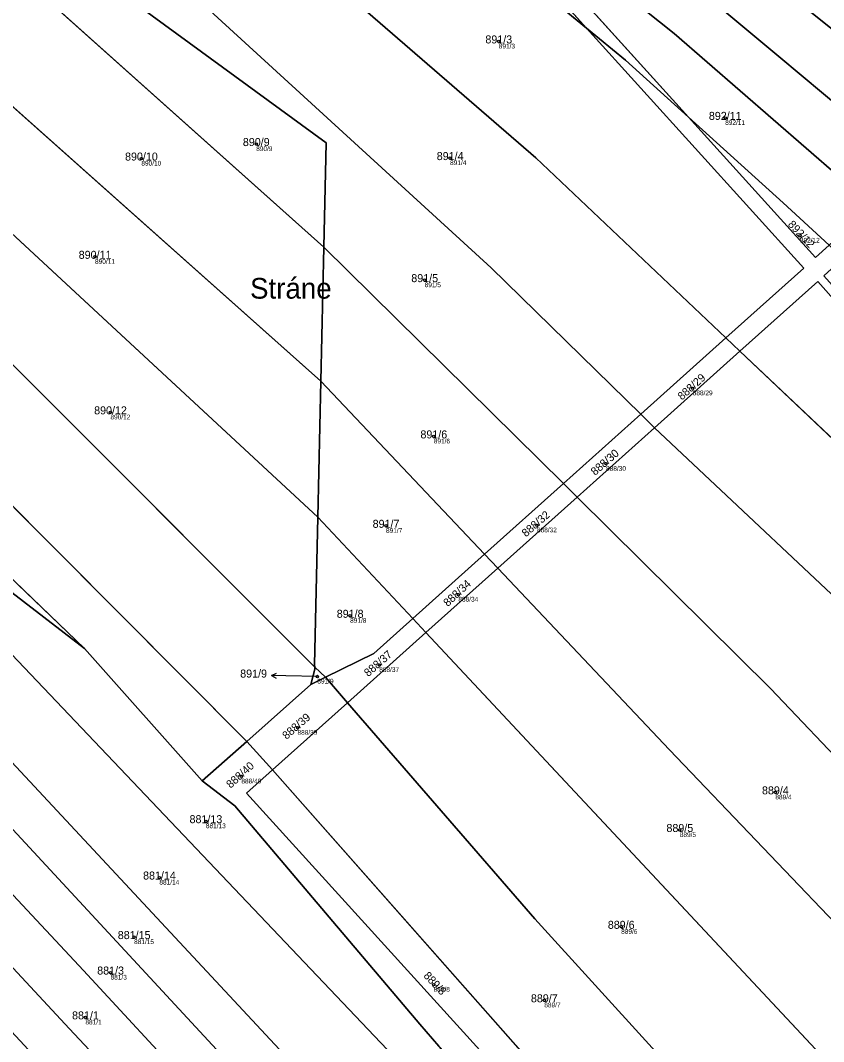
# Model space of a CAD drawing. Extents: x -603967 to -594699, y -1179315 to -1165625.
# Drawn here: x -597688.8 to -597518.2, y -1171449.4 to -1171232.5 of the extents above; entities that cross this region are included whole.
import ezdxf

# ---------------------------------------------------------------- set-up
doc = ezdxf.new("R2010")
doc.units = 0
for name, color, linetype in [('Definiční body', 7, 'Continuous'), ('Hranice parcel', 7, 'Continuous'), ('Parcelní čísla', 7, 'Continuous'), ('Polygon parcely', 7, 'Continuous'), ('Pop  PČ popisy', 7, 'Continuous')]:
    doc.layers.add(name, color=color, linetype=linetype)

msp = doc.modelspace()

# ---------------------------------------------------------------- linework, layer by layer
at = {"layer": 'Definiční body'}
for centre in [(-597587.23, -1171236.96994), (-597539.14, -1171253.20994), (-597638.73, -1171258.76994), (-597663.12, -1171261.84994), (-597597.56, -1171261.74994), (-597523.28, -1171278.20994), (-597672.96, -1171282.71994), (-597602.96, -1171287.67994), (-597546.03, -1171310.63994), (-597669.68, -1171315.75994), (-597601.02, -1171320.86994), (-597564.44, -1171326.67994), (-597579.11, -1171339.74994), (-597611.17, -1171339.85994), (-597595.8, -1171354.45994), (-597618.79, -1171358.96994), (-597612.61, -1171369.41994), (-597625.75, -1171371.86994), (-597629.96, -1171382.74994), (-597641.88, -1171393.08994), (-597528.49, -1171396.47994), (-597649.42, -1171402.59994), (-597548.78, -1171404.46994), (-597659.29, -1171414.56994), (-597561.23, -1171425.03994), (-597664.66, -1171427.21994), (-597669.66, -1171434.74994), (-597601.07, -1171437.31994), (-597577.56, -1171440.64994), (-597675, -1171444.27994)]:
    msp.add_circle(centre, 0.25, dxfattribs=at)
at = {"layer": 'Hranice parcel'}
for p, q in [((-597638.82, -1171176.32), (-597568.57, -1171234.15)), ((-597613.57, -1171184.37), (-597568.57, -1171234.15)), ((-597546.95, -1171253.04), (-597596.69, -1171198.02)), ((-597694.09, -1171218.3), (-597624.36, -1171280.64)), ((-597710.45, -1171233.05), (-597624.99, -1171309.14)), ((-597724.86, -1171246.07), (-597625.64, -1171338.04)), ((-597738.23, -1171257.8), (-597626.31, -1171369.88)), ((-597753.72, -1171272.15), (-597640.75, -1171385.64)), ((-597624.99, -1171309.14), (-597624.36, -1171280.64)), ((-597624.36, -1171280.64), (-597573.47, -1171330.88)), ((-597538.99, -1171299.95), (-597557.08, -1171316.18)), ((-597538.99, -1171299.95), (-597536.01, -1171302.78)), ((-597740.92, -1171302.84), (-597675.16, -1171365.94)), ((-597554.16, -1171319.04), (-597536.01, -1171302.78)), ((-597536.01, -1171302.78), (-597441.73, -1171392.05)), ((-597625.64, -1171338.04), (-597624.99, -1171309.14)), ((-597624.99, -1171309.14), (-597590.23, -1171345.9)), ((-597557.08, -1171316.18), (-597573.47, -1171330.88)), ((-597557.08, -1171316.18), (-597554.16, -1171319.04)), ((-597570.57, -1171333.75), (-597554.16, -1171319.04)), ((-597573.47, -1171330.88), (-597590.23, -1171345.9)), ((-597573.47, -1171330.88), (-597570.57, -1171333.75)), ((-597587.43, -1171348.86), (-597570.57, -1171333.75)), ((-597625.64, -1171338.04), (-597605.49, -1171359.58)), ((-597590.23, -1171345.9), (-597605.49, -1171359.58)), ((-597590.23, -1171345.9), (-597587.43, -1171348.86)), ((-597602.71, -1171362.55), (-597587.43, -1171348.86)), ((-597605.49, -1171359.58), (-597602.71, -1171362.55)), ((-597619.35, -1171377.46), (-597602.71, -1171362.55)), ((-597602.71, -1171362.55), (-597503.62, -1171468.5)), ((-597650.23, -1171394.06), (-597675.16, -1171365.94)), ((-597626.31, -1171369.88), (-597624.05, -1171372.04)), ((-597624.05, -1171372.04), (-597627.15, -1171373.56)), ((-597624.05, -1171372.04), (-597619.35, -1171377.46)), ((-597627.15, -1171373.56), (-597640.75, -1171385.64)), ((-597635.25, -1171391.71), (-597619.35, -1171377.46)), ((-597640.75, -1171385.64), (-597650.23, -1171394.06)), ((-597640.75, -1171385.64), (-597635.25, -1171391.71)), ((-597635.25, -1171391.71), (-597532.51, -1171508.06))]:
    msp.add_line(p, q, dxfattribs=at)
for points in [[(-597619, -1171152.15), (-597495.03, -1171251.51), (-597490.18, -1171255.6)], [(-597625.73, -1171158.41), (-597527.76, -1171240.19), (-597499.3, -1171263.96)], [(-597653.35, -1171197.65), (-597579.35, -1171261.73), (-597538.99, -1171299.95)], [(-597596.69, -1171198.02), (-597549.97, -1171235.28), (-597507.9, -1171271.83)], [(-597675.9, -1171205.37), (-597588.87, -1171285.05), (-597557.08, -1171316.18)], [(-597624.36, -1171280.64), (-597623.87, -1171258.48), (-597687.3, -1171212.14)], [(-597568.57, -1171234.15), (-597560.31, -1171240.95), (-597546.95, -1171253.04)], [(-597568.57, -1171234.15), (-597522.47, -1171285.14), (-597538.99, -1171299.95)], [(-597517.08, -1171280.25), (-597519.96, -1171282.89), (-597546.95, -1171253.04)], [(-597546.95, -1171253.04), (-597526.84, -1171271.23), (-597517.08, -1171280.25)], [(-597785.88, -1171273.72), (-597698.87, -1171358.66), (-597539.28, -1171526.49)], [(-597798.56, -1171286.2), (-597707.11, -1171372.43), (-597548.07, -1171543.16)], [(-597536.01, -1171302.78), (-597519.45, -1171287.94), (-597434.29, -1171384), (-597441.73, -1171392.05)], [(-597557.85, -1171562.02), (-597628.52, -1171485.03), (-597675.4, -1171434.3), (-597721.26, -1171385.23), (-597762.22, -1171345.08), (-597817.7, -1171293.77)], [(-597553.17, -1171552.83), (-597611.02, -1171490.2), (-597718.71, -1171373.87), (-597804.91, -1171293.86)], [(-597823.57, -1171301.41), (-597729.77, -1171391.38), (-597678.47, -1171446.61), (-597562.3, -1171570.48)], [(-597675.16, -1171365.94), (-597731.41, -1171322.64), (-597740.92, -1171302.84)], [(-597820.81, -1171313.44), (-597733.25, -1171401.44), (-597680.8, -1171457.94), (-597637.47, -1171505.28), (-597595.8, -1171550.59), (-597567.3, -1171579.99)], [(-597554.16, -1171319.04), (-597503.7, -1171366.48), (-597459.73, -1171411.51)], [(-597570.57, -1171333.75), (-597529.49, -1171374.44), (-597476.23, -1171430.49)], [(-597626.31, -1171369.88), (-597626.33, -1171369.4), (-597625.64, -1171338.04)], [(-597587.43, -1171348.86), (-597550.95, -1171387.45), (-597491.29, -1171449.91)], [(-597605.49, -1171359.58), (-597613.74, -1171366.98), (-597624.05, -1171372.04)], [(-597627.15, -1171373.56), (-597626.28, -1171370.28), (-597626.31, -1171369.88)], [(-597619.35, -1171377.46), (-597579.59, -1171423.33), (-597518.33, -1171490.67)], [(-597532.51, -1171508.06), (-597536.12, -1171512.02), (-597640.76, -1171396.65), (-597635.25, -1171391.71)], [(-597599.98, -1171450.36), (-597604.01, -1171445.75), (-597643.27, -1171399.35), (-597650.23, -1171394.06)]]:
    msp.add_lwpolyline(points, dxfattribs=at)
at = {"layer": 'Polygon parcely'}
for points in [[(-597490.18, -1171255.6), (-597481.53, -1171247.68), (-597611.54, -1171142.36), (-597619, -1171152.15), (-597495.03, -1171251.51)], [(-597527.76, -1171240.19), (-597499.3, -1171263.96), (-597490.18, -1171255.6), (-597495.03, -1171251.51), (-597619, -1171152.15), (-597619.88, -1171153.3), (-597625.73, -1171158.41)], [(-597507.9, -1171271.83), (-597499.3, -1171263.96), (-597527.76, -1171240.19), (-597625.73, -1171158.41), (-597629.36, -1171161.92), (-597596.69, -1171198.02), (-597549.97, -1171235.28)], [(-597568.57, -1171234.15), (-597613.57, -1171184.37), (-597635.17, -1171166.91), (-597638.82, -1171176.32)], [(-597579.35, -1171261.73), (-597538.99, -1171299.95), (-597522.47, -1171285.14), (-597568.57, -1171234.15), (-597638.82, -1171176.32), (-597638.29, -1171186.95), (-597641.25, -1171190.94), (-597653.35, -1171197.65)], [(-597560.31, -1171240.95), (-597546.95, -1171253.04), (-597596.69, -1171198.02), (-597613.57, -1171184.37), (-597568.57, -1171234.15)], [(-597588.87, -1171285.05), (-597557.08, -1171316.18), (-597538.99, -1171299.95), (-597579.35, -1171261.73), (-597653.35, -1171197.65), (-597671.49, -1171204.29), (-597675.9, -1171205.37)], [(-597517.08, -1171280.25), (-597507.9, -1171271.83), (-597549.97, -1171235.28), (-597596.69, -1171198.02), (-597546.95, -1171253.04), (-597526.84, -1171271.23)], [(-597573.47, -1171330.88), (-597557.08, -1171316.18), (-597588.87, -1171285.05), (-597675.9, -1171205.37), (-597687.3, -1171212.14), (-597623.87, -1171258.48), (-597624.36, -1171280.64)], [(-597694.09, -1171218.3), (-597624.36, -1171280.64), (-597623.87, -1171258.48), (-597687.3, -1171212.14)], [(-597710.45, -1171233.05), (-597624.99, -1171309.14), (-597624.36, -1171280.64), (-597694.09, -1171218.3)], [(-597625.64, -1171338.04), (-597624.99, -1171309.14), (-597710.45, -1171233.05), (-597710.47, -1171233.07), (-597724.86, -1171246.07)], [(-597519.45, -1171287.94), (-597434.29, -1171384), (-597441.73, -1171392.05), (-597438.05, -1171395.53), (-597416.59, -1171374.28), (-597420.76, -1171370.38), (-597432.83, -1171382.26), (-597518.17, -1171286.79), (-597514.06, -1171283.04), (-597517.08, -1171280.25), (-597519.96, -1171282.89), (-597546.95, -1171253.04), (-597560.31, -1171240.95), (-597568.57, -1171234.15), (-597522.47, -1171285.14), (-597538.99, -1171299.95), (-597536.01, -1171302.78)], [(-597625.64, -1171338.04), (-597724.86, -1171246.07), (-597738.23, -1171257.8), (-597626.31, -1171369.88), (-597626.33, -1171369.4)], [(-597546.95, -1171253.04), (-597519.96, -1171282.89), (-597517.08, -1171280.25), (-597526.84, -1171271.23)], [(-597640.75, -1171385.64), (-597627.15, -1171373.56), (-597626.28, -1171370.28), (-597626.31, -1171369.88), (-597738.23, -1171257.8), (-597753.72, -1171272.15)], [(-597539.28, -1171526.49), (-597536.95, -1171522.06), (-597571.65, -1171482.78), (-597599.98, -1171450.36), (-597604.01, -1171445.75), (-597643.27, -1171399.35), (-597650.23, -1171394.06), (-597675.16, -1171365.94), (-597731.41, -1171322.64), (-597740.92, -1171302.84), (-597777.31, -1171267.91), (-597785.88, -1171273.72), (-597698.87, -1171358.66)], [(-597675.16, -1171365.94), (-597650.23, -1171394.06), (-597640.75, -1171385.64), (-597753.72, -1171272.15), (-597755.07, -1171273.4), (-597740.92, -1171302.84)], [(-597707.11, -1171372.43), (-597548.07, -1171543.16), (-597539.28, -1171526.49), (-597698.87, -1171358.66), (-597785.88, -1171273.72), (-597791.14, -1171277.25), (-597798.56, -1171286.2)], [(-597590.23, -1171345.9), (-597573.47, -1171330.88), (-597624.36, -1171280.64), (-597624.99, -1171309.14)], [(-597548.07, -1171543.16), (-597707.11, -1171372.43), (-597798.56, -1171286.2), (-597804.91, -1171293.86), (-597718.71, -1171373.87), (-597611.02, -1171490.2), (-597553.17, -1171552.83)], [(-597441.73, -1171392.05), (-597434.29, -1171384), (-597519.45, -1171287.94), (-597536.01, -1171302.78)], [(-597675.4, -1171434.3), (-597721.26, -1171385.23), (-597762.22, -1171345.08), (-597817.7, -1171293.77), (-597823.57, -1171301.41), (-597729.77, -1171391.38), (-597678.47, -1171446.61), (-597562.3, -1171570.48), (-597557.85, -1171562.02), (-597628.52, -1171485.03)], [(-597553.17, -1171552.83), (-597611.02, -1171490.2), (-597718.71, -1171373.87), (-597804.91, -1171293.86), (-597808.81, -1171298.6), (-597817.7, -1171293.77), (-597762.22, -1171345.08), (-597721.26, -1171385.23), (-597675.4, -1171434.3), (-597628.52, -1171485.03), (-597557.85, -1171562.02)], [(-597538.99, -1171299.95), (-597557.08, -1171316.18), (-597554.16, -1171319.04), (-597536.01, -1171302.78)], [(-597733.25, -1171401.44), (-597680.8, -1171457.94), (-597637.47, -1171505.28), (-597595.8, -1171550.59), (-597567.3, -1171579.99), (-597562.3, -1171570.48), (-597678.47, -1171446.61), (-597729.77, -1171391.38), (-597823.57, -1171301.41), (-597820.81, -1171313.44)], [(-597740.92, -1171302.84), (-597731.41, -1171322.64), (-597675.16, -1171365.94)], [(-597503.7, -1171366.48), (-597459.73, -1171411.51), (-597441.73, -1171392.05), (-597536.01, -1171302.78), (-597554.16, -1171319.04)], [(-597590.23, -1171345.9), (-597624.99, -1171309.14), (-597625.64, -1171338.04), (-597605.49, -1171359.58)], [(-597572.35, -1171589.98), (-597567.48, -1171580.33), (-597567.3, -1171579.99), (-597595.8, -1171550.59), (-597637.47, -1171505.28), (-597680.8, -1171457.94), (-597733.25, -1171401.44), (-597820.81, -1171313.44), (-597818.75, -1171330.98), (-597742.73, -1171403.86)], [(-597557.08, -1171316.18), (-597573.47, -1171330.88), (-597570.57, -1171333.75), (-597554.16, -1171319.04)], [(-597476.23, -1171430.49), (-597467.74, -1171420.18), (-597459.73, -1171411.51), (-597503.7, -1171366.48), (-597554.16, -1171319.04), (-597570.57, -1171333.75), (-597529.49, -1171374.44)], [(-597590.23, -1171345.9), (-597587.43, -1171348.86), (-597570.57, -1171333.75), (-597573.47, -1171330.88)], [(-597491.29, -1171449.91), (-597487.43, -1171444.09), (-597476.23, -1171430.49), (-597529.49, -1171374.44), (-597570.57, -1171333.75), (-597587.43, -1171348.86), (-597550.95, -1171387.45)], [(-597624.05, -1171372.04), (-597613.74, -1171366.98), (-597605.49, -1171359.58), (-597625.64, -1171338.04), (-597626.33, -1171369.4), (-597626.31, -1171369.88)], [(-597587.43, -1171348.86), (-597590.23, -1171345.9), (-597605.49, -1171359.58), (-597602.71, -1171362.55)], [(-597503.62, -1171468.5), (-597491.29, -1171449.91), (-597550.95, -1171387.45), (-597587.43, -1171348.86), (-597602.71, -1171362.55)], [(-597613.74, -1171366.98), (-597624.05, -1171372.04), (-597619.35, -1171377.46), (-597602.71, -1171362.55), (-597605.49, -1171359.58)], [(-597579.59, -1171423.33), (-597518.33, -1171490.67), (-597503.62, -1171468.5), (-597602.71, -1171362.55), (-597619.35, -1171377.46)], [(-597627.15, -1171373.56), (-597624.05, -1171372.04), (-597626.31, -1171369.88), (-597626.28, -1171370.28)], [(-597640.75, -1171385.64), (-597635.25, -1171391.71), (-597619.35, -1171377.46), (-597624.05, -1171372.04), (-597627.15, -1171373.56)], [(-597635.25, -1171391.71), (-597532.51, -1171508.06), (-597522.8, -1171497.41), (-597518.33, -1171490.67), (-597579.59, -1171423.33), (-597619.35, -1171377.46)], [(-597536.12, -1171512.02), (-597640.76, -1171396.65), (-597635.25, -1171391.71), (-597640.75, -1171385.64), (-597650.23, -1171394.06), (-597643.27, -1171399.35), (-597604.01, -1171445.75), (-597599.98, -1171450.36), (-597530.86, -1171523.81), (-597529.58, -1171521.69), (-597525.22, -1171516.31), (-597532.51, -1171508.06)], [(-597635.25, -1171391.71), (-597640.76, -1171396.65), (-597536.12, -1171512.02), (-597532.51, -1171508.06)]]:
    msp.add_lwpolyline(points, close=True, dxfattribs=at)
at = {"layer": 'Pop  PČ popisy'}
for p, q in [((-597635.461, -1171371.678), (-597634.45, -1171371.194)), ((-597632.46, -1171371.73), (-597635.461, -1171371.678)), ((-597635.461, -1171371.678), (-597634.468, -1171372.196)), ((-597625.75, -1171371.87), (-597632.46, -1171371.73))]:
    msp.add_line(p, q, dxfattribs=at)

# ---------------------------------------------------------------- texts
at = {"layer": 'Definiční body'}
for s, p in [('891/3', (-597587.23, -1171238.459)), ('892/11', (-597539.14, -1171254.699)), ('890/9', (-597638.73, -1171260.259)), ('890/10', (-597663.12, -1171263.339)), ('891/4', (-597597.56, -1171263.239)), ('892/12', (-597523.28, -1171279.699)), ('890/11', (-597672.96, -1171284.209)), ('891/5', (-597602.96, -1171289.169)), ('888/29', (-597546.03, -1171312.129)), ('890/12', (-597669.68, -1171317.249)), ('891/6', (-597601.02, -1171322.359)), ('888/30', (-597564.44, -1171328.169)), ('891/7', (-597611.17, -1171341.349)), ('888/32', (-597579.11, -1171341.239)), ('888/34', (-597595.8, -1171355.949)), ('891/8', (-597618.79, -1171360.459)), ('888/37', (-597612.61, -1171370.909)), ('891/9', (-597625.75, -1171373.359)), ('888/39', (-597629.96, -1171384.239)), ('888/40', (-597641.88, -1171394.579)), ('889/4', (-597528.49, -1171397.969)), ('881/13', (-597649.42, -1171404.089)), ('889/5', (-597548.78, -1171405.959)), ('881/14', (-597659.29, -1171416.059)), ('889/6', (-597561.23, -1171426.529)), ('881/15', (-597664.66, -1171428.709)), ('881/3', (-597669.66, -1171436.239)), ('889/8', (-597601.07, -1171438.809)), ('889/7', (-597577.56, -1171442.139)), ('881/1', (-597675, -1171445.769))]:
    msp.add_text(s, height=0.999996, dxfattribs=at).set_placement(p)
at = {"layer": 'Parcelní čísla'}
for s, p in [('891/3', (-597590.066, -1171237.395)), ('892/11', (-597542.606, -1171253.635)), ('890/9', (-597641.566, -1171259.195)), ('890/10', (-597666.586, -1171262.275)), ('891/4', (-597600.396, -1171262.175)), ('890/11', (-597676.426, -1171283.145)), ('891/5', (-597605.796, -1171288.105)), ('890/12', (-597673.146, -1171316.185)), ('891/6', (-597603.856, -1171321.295)), ('891/7', (-597614.006, -1171340.285)), ('891/8', (-597621.626, -1171359.395)), ('891/9', (-597642.132, -1171372.095)), ('889/4', (-597531.326, -1171396.905)), ('881/13', (-597652.886, -1171403.025)), ('889/5', (-597551.616, -1171404.895)), ('881/14', (-597662.756, -1171414.995)), ('889/6', (-597564.066, -1171425.465)), ('881/15', (-597668.126, -1171427.645)), ('881/3', (-597672.496, -1171435.175)), ('889/7', (-597580.396, -1171441.075)), ('881/1', (-597677.836, -1171444.705))]:
    msp.add_text(s, height=1.699998, dxfattribs=at).set_placement(p)
for s, rotation, p in [('892/12', 313, (-597525.954, -1171275.964)), ('888/29', 42, (-597548.321, -1171313.275)), ('888/30', 41, (-597566.777, -1171329.274)), ('888/32', 41, (-597581.447, -1171342.344)), ('888/34', 43, (-597598.045, -1171357.134)), ('888/37', 41, (-597614.947, -1171372.014)), ('888/39', 41, (-597632.297, -1171385.344)), ('888/40', 42, (-597644.171, -1171395.725)), ('889/8', 313, (-597603.315, -1171435.535))]:
    msp.add_text(s, height=1.699998, rotation=rotation, dxfattribs=at).set_placement(p)
at = {"layer": 'Pop  PČ popisy'}
msp.add_text('Stráne', height=4.399998, dxfattribs=at).set_placement((-597640.042, -1171291.61))

doc.saveas('drawing.dxf')
